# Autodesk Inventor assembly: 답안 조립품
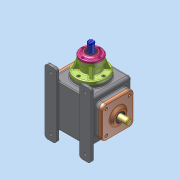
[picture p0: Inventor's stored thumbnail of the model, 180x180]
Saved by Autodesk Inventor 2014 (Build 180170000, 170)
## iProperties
Created: 2026-05
Part Number: 답안 조립품
Document SubType Name: Assembly
Designer: dg
Mass: 6737.06 g
Surface Area: 5034.42 cm^2
Volume: 1833.45 cm^3
Density: 3.67452 g/cm^3
Author: dg
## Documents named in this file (16)
- C:\Users\dg\Desktop\660503V1004\답안 조립품.iam
- C:\Users\dg\Desktop\660503V1004\Imported Components\본체\본체.ipt
- C:\Users\dg\Desktop\660503V1004\Imported Components\종동축\종동축.ipt
- C:\Users\dg\Desktop\660503V1004\Imported Components\테이퍼 롤러 베어링 30204K\테이퍼 롤러 베어링 30204K.ipt
- C:\Users\dg\Desktop\660503V1004\Imported Components\측면 커버\측면 커버.ipt
- C:\Users\dg\Desktop\660503V1004\Imported Components\베벨 기어(종동)\베벨 기어(종동).ipt
- C:\Users\dg\Desktop\660503V1004\Imported Components\칼라\칼라.ipt
- C:\Users\dg\Desktop\660503V1004\Imported Components\베어링 하우징\베어링 하우징.ipt
- C:\Users\dg\Desktop\660503V1004\Imported Components\하우징 커버\하우징 커버.ipt
- C:\Users\dg\Desktop\660503V1004\Imported Components\구동축\구동축.ipt
- C:\Users\dg\Desktop\660503V1004\Imported Components\오일 실 20 35 8\오일 실 20 35 8.ipt
- C:\Users\dg\Desktop\660503V1004\Imported Components\베벨 기어(구동)\베벨 기어(구동).ipt
- C:\Users\dg\Desktop\660503V1004\Imported Components\평행 키 6x6x18\평행 키 6x6x18.ipt
- C:\Users\dg\Desktop\660503V1004\Imported Components\6각 구멍붙이 볼트 M6x12\6각 구멍붙이 볼트 M6x12.ipt
- C:\Users\dg\Desktop\660503V1004\Imported Components\엔드캡\엔드캡.ipt
- C:\Users\dg\Desktop\660503V1004\Imported Components\6각 구멍붙이 볼트 M4x10\6각 구멍붙이 볼트 M4x10.ipt
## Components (19 placed, 4 different names)
1. 하우징 커버:1
2. 구동축:1
3. 6각 구멍붙이 볼트 M6x12:1
4. 6각 구멍붙이 볼트 M4x10:1
5. 6각 구멍붙이 볼트 M4x10:2
6. 6각 구멍붙이 볼트 M4x10:3
7. 6각 구멍붙이 볼트 M4x10:4
8. 6각 구멍붙이 볼트 M6x12:3
9. 6각 구멍붙이 볼트 M6x12:5
10. 6각 구멍붙이 볼트 M6x12:6
11. 6각 구멍붙이 볼트 M6x12:7
12. 6각 구멍붙이 볼트 M6x12:2
13. 6각 구멍붙이 볼트 M6x12:8
14. 6각 구멍붙이 볼트 M6x12:9
15. 6각 구멍붙이 볼트 M6x12:10
16. 6각 구멍붙이 볼트 M6x12:4
17. 6각 구멍붙이 볼트 M6x12:11
18. 6각 구멍붙이 볼트 M6x12:12
19. 6각 구멍붙이 볼트 M6x12:13
